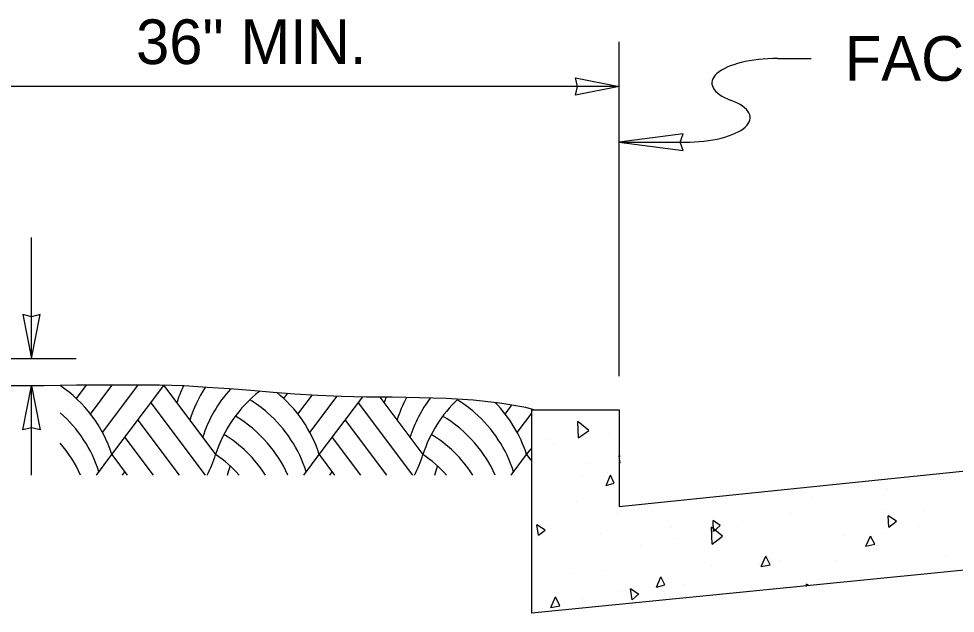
# Model space of a CAD drawing. Extents: x 99862 to 103151, y 100000 to 102076.
# Drawn here: x 100452.7 to 100788.1, y 100711.2 to 100924.1 of the extents above; entities that cross this region are included whole.
import ezdxf

# ---------------------------------------------------------------- set-up
doc = ezdxf.new("R2010")
doc.units = 0
for name, color, linetype in [('Level 10', 7, 'Continuous'), ('Level 14', 7, 'Continuous'), ('Level 15', 7, 'Continuous'), ('Level 17', 7, 'Continuous'), ('Level 20', 7, 'Continuous'), ('Level 28', 7, 'Continuous'), ('Level 8', 7, 'Continuous')]:
    doc.layers.add(name, color=color, linetype=linetype)

msp = doc.modelspace()

# ---------------------------------------------------------------- linework, layer by layer
at = {"layer": 'Level 10'}
for p, q in [((100653.22, 100773.95), (100652.91, 100779.83)), ((100656.92, 100776.62), (100652.91, 100779.83)), ((100653.22, 100773.95), (100656.92, 100776.62)), ((100653.22, 100776.07), (100653.22, 100776.07)), ((100642.86, 100773.45), (100642.86, 100773.45)), ((100664.38, 100775.3), (100664.38, 100775.3)), ((100644.16, 100772.1), (100644.16, 100772.1)), ((100668.11, 100764.93), (100667.81, 100767.56)), ((100668.11, 100767.31), (100667.81, 100767.56)), ((100656.12, 100764.66), (100656.12, 100764.66)), ((100654.79, 100760.41), (100654.79, 100760.41)), ((100663.06, 100756.92), (100664.63, 100760.68)), ((100663.54, 100761.73), (100663.54, 100761.73)), ((100665.98, 100757.72), (100664.63, 100760.68)), ((100771.29, 100759.05), (100771.29, 100759.05)), ((100782.69, 100759.05), (100782.69, 100759.05)), ((100663.06, 100756.92), (100665.98, 100757.72)), ((100763.86, 100755.83), (100763.86, 100755.83)), ((100718.87, 100754.02), (100718.87, 100754.02)), ((100736.19, 100754.8), (100736.19, 100754.8)), ((100736.47, 100752.17), (100736.47, 100752.17)), ((100652.42, 100751.1), (100652.42, 100751.1)), ((100667.03, 100747.33), (100667.03, 100747.33)), ((100729.01, 100747.08), (100729.01, 100747.08)), ((100737.52, 100746.28), (100737.52, 100746.28)), ((100763.06, 100748.41), (100763.06, 100748.41)), ((100764.38, 100742.02), (100764.13, 100746.03)), ((100767.03, 100744.15), (100764.13, 100746.03)), ((100777.14, 100748.16), (100777.14, 100748.16)), ((100638.84, 100739.12), (100638.32, 100742.82)), ((100641.22, 100740.95), (100638.32, 100742.82)), ((100642.86, 100742.58), (100642.86, 100742.58)), ((100701.59, 100740.45), (100701.36, 100744.43)), ((100703.97, 100742.58), (100701.36, 100744.43)), ((100701.59, 100740.45), (100703.97, 100742.58)), ((100707.73, 100742.82), (100707.73, 100742.82)), ((100711.99, 100744.15), (100711.99, 100744.15)), ((100764.38, 100742.02), (100767.03, 100744.15)), ((100774.77, 100742.58), (100774.77, 100742.58)), ((100638.84, 100739.12), (100641.22, 100740.95)), ((100660.93, 100739.9), (100660.93, 100739.9)), ((100686.46, 100742.02), (100686.46, 100742.02)), ((100701.07, 100735.92), (100700.79, 100742.02)), ((100704.81, 100738.82), (100700.79, 100742.02)), ((100701.07, 100735.92), (100704.81, 100738.82)), ((100748.41, 100739.12), (100748.41, 100739.12)), ((100756.12, 100735.15), (100757.76, 100738.82)), ((100759.29, 100735.92), (100757.76, 100738.82)), ((100762.01, 100739.9), (100762.01, 100739.9)), ((100638.32, 100738.32), (100638.32, 100738.32)), ((100675.54, 100735.4), (100675.54, 100735.4)), ((100688.58, 100738.05), (100688.58, 100738.05)), ((100756.12, 100735.15), (100759.29, 100735.92)), ((100679.03, 100734.32), (100679.03, 100734.32)), ((100776.32, 100734.32), (100776.32, 100734.32)), ((100718.09, 100729.01), (100718.09, 100729.01)), ((100718.62, 100727.93), (100720.22, 100731.66)), ((100719.69, 100729.81), (100719.69, 100729.81)), ((100721.83, 100728.48), (100720.22, 100731.66)), ((100725.26, 100730.06), (100725.26, 100730.06)), ((100745.48, 100730.06), (100745.48, 100730.06)), ((100784.58, 100731.95), (100784.58, 100731.95)), ((100661.73, 100726.63), (100661.73, 100726.63)), ((100674.18, 100725.81), (100674.18, 100725.81)), ((100700.79, 100728.18), (100700.79, 100728.18)), ((100707.98, 100727.93), (100707.98, 100727.93)), ((100718.62, 100727.93), (100721.83, 100728.48)), ((100760.66, 100726.05), (100760.66, 100726.05)), ((100650.28, 100725.28), (100650.28, 100725.28)), ((100681.16, 100720.5), (100682.69, 100724.23)), ((100684.06, 100721.31), (100682.69, 100724.23)), ((100753.99, 100723.43), (100753.99, 100723.43)), ((100667.56, 100718.9), (100667.56, 100718.9)), ((100672.37, 100716), (100671.81, 100719.97)), ((100674.77, 100717.85), (100671.81, 100719.97)), ((100681.16, 100720.5), (100684.06, 100721.31)), ((100690.96, 100721.31), (100690.96, 100721.31)), ((100717.04, 100719.42), (100717.04, 100719.42)), ((100734.84, 100720.75), (100734.84, 100721.55)), ((100735.64, 100721.02), (100734.84, 100721.55)), ((100643.34, 100713.28), (100644.98, 100717.05)), ((100646.53, 100713.87), (100644.98, 100717.05)), ((100654.54, 100716), (100654.54, 100716)), ((100672.37, 100716), (100674.77, 100718.12)), ((100691.52, 100717.3), (100691.52, 100717.3)), ((100640.46, 100713.03), (100640.46, 100713.03)), ((100643.34, 100713.28), (100646.53, 100713.87)), ((100665.98, 100715.17), (100665.98, 100715.17))]:
    msp.add_line(p, q, dxfattribs=at)
at = {"layer": 'Level 14'}
for p, q in [((100724.54, 100909.87), (100736.54, 100909.87)), ((100667.81, 100879.87), (100691.24, 100879.87))]:
    msp.add_line(p, q, dxfattribs=at)
msp.add_lwpolyline([(100667.81, 100879.87), (100690.64, 100876.89), (100689.58, 100879.87), (100690.64, 100882.86)], close=True, dxfattribs=at)
for centre, start_param, end_param in [((100724.38, 100901.09), 4.705244, 7.068624), ((100691.24, 100888.66), 1.570796, 3.926959)]:
    msp.add_ellipse(centre, major_axis=(-23.43, 0), ratio=0.375, start_param=start_param, end_param=end_param, dxfattribs=at)
at = {"layer": 'Level 15'}
for p, q in [((100667.81, 100796.08), (100667.81, 100915.87)), ((100667.81, 100899.87), (100404.28, 100899.87)), ((100457.28, 100802.4), (100457.28, 100845.73)), ((100433.01, 100802.4), (100473.28, 100802.4)), ((100457.28, 100760.6), (100457.28, 100792.6))]:
    msp.add_line(p, q, dxfattribs=at)
for points in [[(100667.81, 100899.87), (100652.08, 100896.79), (100652.81, 100899.87), (100652.08, 100902.96)], [(100457.28, 100802.4), (100460.37, 100818.12), (100457.28, 100817.39), (100454.2, 100818.12)], [(100457.28, 100792.6), (100460.37, 100776.87), (100457.28, 100777.6), (100454.2, 100776.87)]]:
    msp.add_lwpolyline(points, close=True, dxfattribs=at)
at = {"layer": 'Level 17'}
msp.add_lwpolyline([(100808.23, 100727.93), (100799.72, 100727.41), (100636.47, 100711.16), (100636.47, 100784.08), (100667.81, 100784.08), (100667.81, 100749.46), (100797.59, 100762.81), (100797.91, 100762.81)], dxfattribs=at)
at = {"layer": 'Level 28'}
for p, q in [((100473.38, 100788.1), (100476.84, 100792.72)), ((100476.84, 100792.72), (100476.9, 100792.79)), ((100478.48, 100782.53), (100486.12, 100792.72)), ((100482.78, 100775.89), (100495.41, 100792.72)), ((100486.12, 100792.72), (100486.21, 100792.84)), ((100486.12, 100767.97), (100504.69, 100792.72)), ((100495.41, 100792.72), (100495.45, 100792.79)), ((100504.67, 100792.74), (100504.69, 100792.72)), ((100504.69, 100792.72), (100523.25, 100767.97)), ((100547.63, 100788.1), (100549.07, 100790.03)), ((100552.72, 100782.53), (100557.89, 100789.41)), ((100500.05, 100786.54), (100519.45, 100760.66)), ((100557.03, 100775.89), (100566.8, 100788.92)), ((100560.37, 100767.97), (100575.95, 100788.74)), ((100574.29, 100786.54), (100593.7, 100760.66)), ((100582, 100788.62), (100597.49, 100767.97)), ((100626.97, 100782.53), (100629.26, 100785.58)), ((100631.27, 100775.89), (100636.45, 100782.79)), ((100495.41, 100780.35), (100510.17, 100760.66)), ((100569.65, 100780.35), (100584.42, 100760.66)), ((100490.77, 100774.16), (100500.89, 100760.66)), ((100565.01, 100774.16), (100575.14, 100760.66)), ((100634.61, 100767.97), (100636.21, 100770.09)), ((100480.64, 100760.66), (100486.12, 100767.97)), ((100486.12, 100767.97), (100491.61, 100760.66)), ((100554.88, 100760.66), (100560.37, 100767.97)), ((100560.37, 100767.97), (100565.86, 100760.66)), ((100629.13, 100760.66), (100634.61, 100767.97)), ((100634.61, 100767.97), (100636.13, 100765.96)), ((100489.92, 100760.66), (100490.77, 100761.79)), ((100564.16, 100760.66), (100565.01, 100761.79))]:
    msp.add_line(p, q, dxfattribs=at)
for centre, start, end in [((100441.36, 100753.74), 56.0955, 56.0963), ((100441.36, 100753.74), 17.6434, 56.0955), ((100549.45, 100778.49), 162.3369, 162.3566), ((100554.09, 100772.3), 154.5447, 162.3566), ((100558.73, 100766.11), 146.5041, 162.3566), ((100563.37, 100759.92), 137.823, 162.3566), ((100568.01, 100753.74), 128.0476, 162.3566), ((100515.61, 100753.74), 17.6434, 51.1251), ((100510.97, 100747.55), 48.9597, 58.5465), ((100628.33, 100772.3), 159.7177, 162.3566), ((100632.97, 100766.11), 151.62, 162.3566), ((100637.61, 100759.92), 142.9394, 162.3566), ((100642.26, 100753.74), 133.4703, 162.3566), ((100585.21, 100747.55), 48.9597, 58.5465), ((100589.85, 100753.74), 17.6434, 44.4646), ((100436.72, 100747.55), 17.6434, 48.9588), ((100510.97, 100747.55), 17.6434, 48.9597), ((100585.21, 100747.55), 17.6434, 48.9597), ((100506.33, 100741.36), 40.9413, 59.3021), ((100580.57, 100741.36), 40.9413, 59.3021), ((100501.69, 100735.18), 32.8557, 58.4874), ((100575.93, 100735.18), 32.8557, 58.4874), ((100432.08, 100741.36), 24.2553, 40.9403), ((100506.33, 100741.36), 24.2553, 40.9414), ((100580.57, 100741.36), 24.2553, 40.9414), ((100478.49, 100782.21), 332.6888, 342.3566), ((100497.05, 100728.99), 42.3956, 56.0964), ((100552.73, 100782.21), 332.6888, 342.3566), ((100571.29, 100728.99), 42.3956, 56.0964), ((100483.13, 100776.02), 340.907, 345.0113), ((100557.37, 100776.02), 340.907, 345.0113)]:
    msp.add_arc(centre, 46.97, start, end, dxfattribs=at)
at = {"layer": 'Level 8'}
msp.add_lwpolyline([(100637.24, 100784.08), (100634.34, 100784.86), (100625.01, 100786.46), (100615.44, 100787.51), (100605.86, 100788.06), (100596.29, 100788.35), (100586.46, 100788.58), (100577.14, 100788.58), (100568.38, 100788.83), (100559.88, 100789.11), (100551.61, 100789.63), (100543.91, 100790.2), (100535.88, 100790.96), (100528.21, 100791.52), (100520.22, 100792.01), (100511.98, 100792.6), (100503.19, 100792.85), (100493.92, 100792.85), (100484.04, 100792.85), (100473.41, 100792.85), (100461.72, 100792.6), (100448.96, 100792.6)], dxfattribs=at)

# ---------------------------------------------------------------- texts
at = {"layer": 'Level 20'}
for s, p in [('36" MIN.', (100494.75, 100907.87)), ('FACE OF CURB', (100748.54, 100901.87))]:
    msp.add_text(s, height=16, dxfattribs=at).set_placement(p)

doc.saveas('drawing.dxf')
